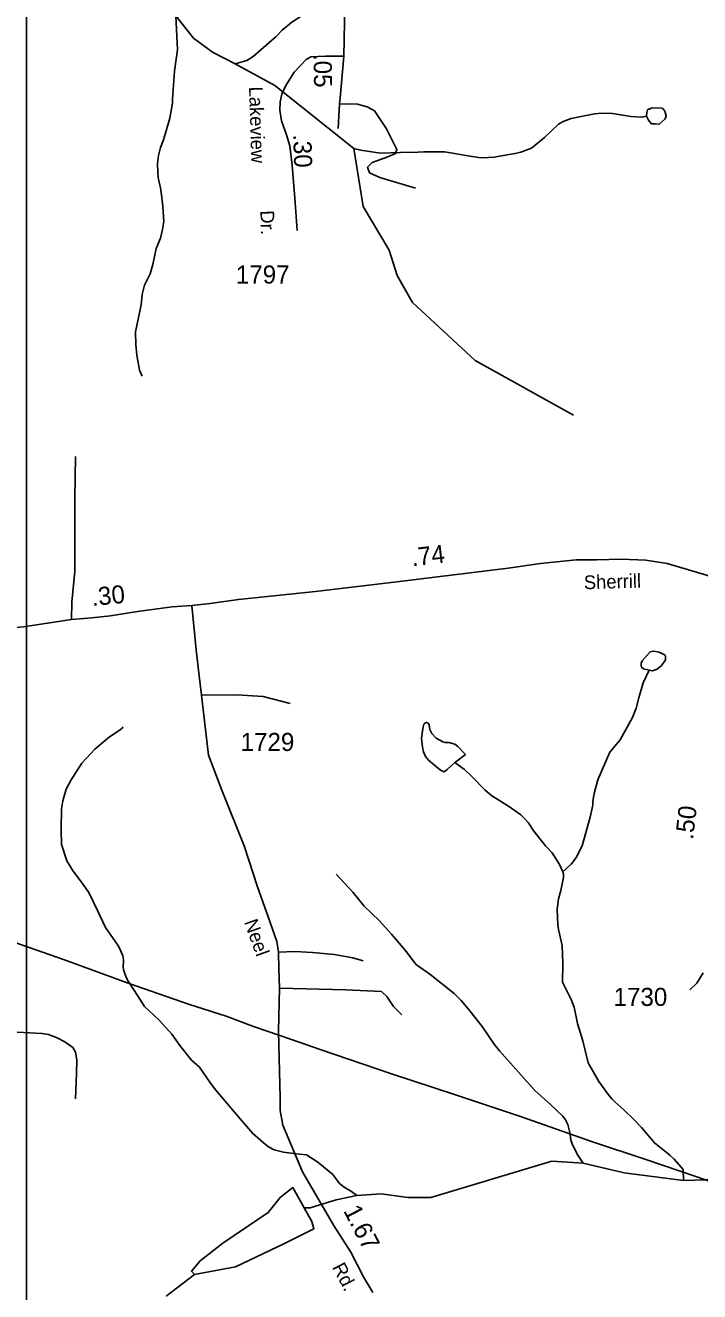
# Model space of a CAD drawing. Extents: x 1473865 to 1648260, y 639067 to 773536.
# Drawn here: x 1530800 to 1535463, y 703860 to 712614 of the extents above; entities that cross this region are included whole.
import ezdxf

# ---------------------------------------------------------------- set-up
doc = ezdxf.new("R2010")
doc.units = 0
for name, color, linetype in [('Exist Hydrographic Creek Single Shore', 7, 'Continuous'), ('Exist Hydrographic Misc Water Feature', 7, 'Continuous'), ('Exist Hydrographic Pond Under 1500 Sq Ft', 7, 'Continuous'), ('Exist Road Non-System Type 51', 7, 'Continuous'), ('Exist Road Secondary Mileage Hundredths English Label', 7, 'Continuous'), ('Exist Road Secondary Type 51 Attributed', 7, 'Continuous'), ('Exist Road Secondary Type 51 Label', 7, 'Continuous'), ('Exist Road Secondary Type 51 Number Label', 7, 'Continuous'), ('Exist Utilities Electrical Transmission Line', 7, 'Continuous'), ('Map Preparation Inset Cut Line', 7, 'Continuous')]:
    doc.layers.add(name, color=color, linetype=linetype)

msp = doc.modelspace()

# ---------------------------------------------------------------- linework, layer by layer
at = {"layer": 'Exist Hydrographic Creek Single Shore'}
for points in [[(1534589.6, 709919.7), (1533911.6, 710297.7), (1533476.6, 710697.1), (1533370.7, 710883.1), (1533315.6, 711058.2), (1533136.6, 711360.5), (1533071.2, 711761.9), (1532524.6, 712196.7), (1532250.4, 712346.9), (1532094.6, 712428.7), (1531963.7, 712525.7), (1531840.7, 712679.1)], [(1537312.6, 702324.8), (1537305.6, 702384), (1537166.6, 702560.8), (1537036.6, 702786.6), (1536651.6, 703227.7), (1536390.6, 703590.8), (1536244.6, 703849.7), (1536031.6, 704103.5), (1535822.6, 704567.3), (1535733.4, 704640.1), (1535350.5, 704627.4), (1534940.5, 704680.2), (1534657.6, 704746.9), (1534441.5, 704762.6), (1533603.6, 704510.3), (1533445.5, 704510.3), (1533260.5, 704535.4), (1533093.2, 704523.7), (1532948.5, 704494.9), (1532769.6, 704438.5), (1532727.5, 704439.4)]]:
    msp.add_lwpolyline(points, dxfattribs=at)
at = {"layer": 'Exist Hydrographic Misc Water Feature'}
for points in [[(1532250.4, 712346.9), (1532330.8, 712371.3), (1532375.3, 712398.4), (1532534.2, 712537.1), (1532575, 712580.2), (1532642, 712634.8), (1532715, 712681.3), (1532757.4, 712702.4), (1532890.5, 712757.8), (1532959, 712782.3), (1533019.2, 712791.1), (1533063.6, 712810.2), (1533133.3, 712900.7), (1533171.1, 712995.9), (1533200.8, 713075.3), (1533237, 713114.4)], [(1531840.7, 712679.1), (1531852.2, 712444.7), (1531841.4, 712363.2), (1531830.5, 712296.2), (1531817.5, 712103.8), (1531817, 712075.9), (1531798.9, 711972.3), (1531790.3, 711940.5), (1531756, 711821.2), (1531735, 711769.7), (1531721.6, 711714.3), (1531712.8, 711658.2), (1531715.6, 711596.1), (1531719, 711562.1), (1531722.5, 711538), (1531733.5, 711489.8), (1531740.6, 711441.7), (1531751.1, 711361.5), (1531757, 711257.4), (1531748, 711201.7), (1531734.8, 711142), (1531705.4, 711070.6), (1531692.3, 711014.9), (1531681.2, 710959.1), (1531662, 710895.6), (1531624.4, 710816.4), (1531607.2, 710752.7), (1531600.1, 710680.9), (1531562.1, 710493.8), (1531564.5, 710405.8), (1531567.5, 710357.7), (1531571, 710333.7), (1531589, 710229.4), (1531608.2, 710189)], [(1533071.2, 711761.9), (1533119, 711749.6), (1533254.2, 711729.2), (1533394.7, 711734), (1533514.8, 711737.5), (1533554.8, 711738.7), (1533594.9, 711739.9), (1533698.8, 711739.8), (1533889.4, 711706.5), (1533950.1, 711698.7), (1534002.1, 711699.6), (1534042.2, 711702.8), (1534066.3, 711706.4), (1534146.6, 711720.7), (1534186.8, 711727.9), (1534227, 711737.1), (1534299.4, 711763.6), (1534389.3, 711838.8), (1534486.8, 711929.7), (1534519.2, 711949), (1534575.5, 711969.9), (1534712.1, 711997.1), (1534736.2, 712000.6), (1534784.3, 712005.6), (1534860.3, 712004.1), (1534987.9, 711983.8), (1535063.8, 711977.9), (1535096.2, 711984.8)], [(1535097.3, 712010.9), (1535096.2, 711984.8), (1535108.7, 711957.9), (1535128.8, 711933), (1535157.9, 711933.7), (1535183.4, 711930.1), (1535224.5, 711968.3), (1535230.9, 711988.2), (1535221.5, 712020.4), (1535207.9, 712038.7), (1535199.9, 712040.8), (1535131.9, 712042.2), (1535115.7, 712034.5), (1535107.7, 712034.7), (1535101.7, 712028.8), (1535097.3, 712010.9)], [(1535113.5, 708154.8), (1535073.7, 708165.5), (1535061.8, 708175.8), (1535058, 708185.8), (1535058.4, 708203.8), (1535064.7, 708219.7), (1535120, 708282.6), (1535144.1, 708288), (1535183.9, 708281.2), (1535223.5, 708258.5), (1535227.4, 708250.4), (1535226.9, 708228.4), (1535218.6, 708212.6), (1535200.1, 708188.9), (1535169.7, 708163.6), (1535137.4, 708152.2), (1535113.5, 708154.8)], [(1534516.7, 706762.8), (1534573.3, 706814.3), (1534587.6, 706832), (1534597.9, 706845.8), (1534608.3, 706861.6), (1534649.8, 706940.7), (1534705.7, 707139.5), (1534723.3, 707223.1), (1534723.7, 707247.1), (1534728.3, 707279), (1534732.8, 707302.9), (1534758.7, 707398.3), (1534842.1, 707588.5), (1534913.6, 707674.4), (1534999.1, 707829.2), (1535024.4, 707892.6), (1535041.7, 707964.3), (1535071.8, 708067.6), (1535113.5, 708154.8)], [(1533093.2, 704523.7), (1533055, 704552.2), (1533003.5, 704581.3), (1532972, 704607.9), (1532925.2, 704668.8), (1532822.9, 704754.8), (1532743.8, 704804.4), (1532695.8, 704809.4), (1532671.9, 704811.9), (1532584.1, 704823.6), (1532520.4, 704841), (1532480.8, 704861.7), (1532461.1, 704876.1), (1532372.9, 704951.9), (1532284.5, 705053.6), (1532116.4, 705253), (1532081.3, 705301.7), (1532003.4, 705411.2), (1531948.3, 705460.3), (1531868.3, 705561.8), (1531811.8, 705639), (1531725.6, 705736.7), (1531623.5, 705830.7), (1531553.6, 705940), (1531506.9, 706013), (1531491.6, 706045.3), (1531480.3, 706077.5), (1531476.7, 706099.6), (1531477.7, 706153.5), (1531474.2, 706181.5), (1531453.2, 706230), (1531439.7, 706254.2), (1531354, 706375.9), (1531300.3, 706489), (1531238.7, 706618.1), (1531182.2, 706699.2), (1531129.5, 706766.3), (1531086.9, 706837.1), (1531049.1, 706949.8), (1531047.1, 707053.8), (1531049.9, 707197.7), (1531059, 707253.5), (1531082.6, 707333), (1531116.8, 707397.9), (1531190.3, 707513.6), (1531280, 707608.9), (1531381.7, 707694.7), (1531454.7, 707743.2), (1531470.9, 707756.9), (1531475.1, 707764.8)], [(1533770.3, 707517.3), (1533776.9, 707522.2), (1533842.7, 707574), (1533790.9, 707627.8), (1533769.3, 707644.3), (1533727.5, 707655.1), (1533703.5, 707655.6), (1533687.6, 707659.9), (1533640, 707686.9), (1533610.7, 707717.5), (1533597.1, 707745.7), (1533591.8, 707777.8), (1533582.1, 707792), (1533574.1, 707794.2), (1533562.1, 707790.4), (1533555.9, 707782.5), (1533549.3, 707750.7), (1533540, 707686.9), (1533546.8, 707622.8), (1533554.2, 707590.7), (1533567.5, 707558.4), (1533587.1, 707534), (1533669.7, 707464.4), (1533695.6, 707453.8), (1533717.8, 707469.4), (1533770.3, 707517.3)], [(1534516.7, 706762.8), (1534493.2, 706812), (1534442.8, 706893), (1534397.8, 706941.8), (1534315.6, 707043.5), (1534276.8, 707102.2), (1534253.3, 707128.7), (1534225.8, 707155.2), (1534141, 707216.9), (1534026.3, 707287.2), (1533980.8, 707326.1), (1533887.5, 707421.6), (1533835.8, 707469), (1533770.3, 707517.3)], [(1534657.6, 704746.9), (1534620.2, 704804.3), (1534581.6, 704879), (1534570.4, 704919.3), (1534567, 704951.3), (1534552.3, 705015.6), (1534534.9, 705047.9), (1534517.4, 705072.3), (1534431, 705154), (1534322.8, 705250.1), (1534078.1, 705525), (1534042.9, 705569.7), (1533959.4, 705693.3), (1533873.4, 705801), (1533814.8, 705872.2), (1533765.7, 705921.1), (1533596.3, 706054.5), (1533505.5, 706118.3), (1533487.8, 706136.7), (1533435.3, 706207.7), (1533359, 706299.2), (1533331.6, 706331.8), (1533247.4, 706425.4), (1533143.3, 706523.5), (1533065.1, 706621.1), (1532949.6, 706745.3)], [(1535350.5, 704627.4), (1535348.4, 704703.6), (1535287.8, 704774.8), (1535256.3, 704803.4), (1535149.9, 704887.5), (1535060, 704993.3), (1535009, 705046.3), (1534938.4, 705117.7), (1534875.4, 705170.9), (1534857.7, 705189.3), (1534832.4, 705219.8), (1534766.1, 705313.1), (1534692.6, 705440.5), (1534655.5, 705593.2), (1534617.9, 705713.9), (1534596.1, 705826.3), (1534577, 705874.7), (1534515.5, 705999.9), (1534517.9, 706127.8), (1534512.3, 706251.8), (1534486.6, 706364.3), (1534483.1, 706394.3), (1534476.7, 706504.7), (1534486.7, 706576.2), (1534503.5, 706632.1), (1534521.5, 706723.4), (1534521.9, 706747.4), (1534516.7, 706762.8)], [(1531969.8, 703978.6), (1531773.1, 703828)]]:
    msp.add_lwpolyline(points, dxfattribs=at)
at = {"layer": 'Exist Hydrographic Pond Under 1500 Sq Ft'}
msp.add_lwpolyline([(1532727.5, 704439.4), (1532781.9, 704343.5), (1532795.9, 704295), (1532738.8, 704267.2), (1532588.3, 704189.1), (1532252.6, 704030.2), (1531969.8, 703978.6), (1531948.6, 704001.5), (1532009, 704073.6), (1532166.2, 704195.7), (1532479.6, 704406.2), (1532561.8, 704510.8), (1532649.6, 704579.1), (1532727.5, 704439.4)], dxfattribs=at)
at = {"layer": 'Exist Road Non-System Type 51'}
for points in [[(1532973.5, 712071.3), (1532962.8, 711901.2)], [(1532976.4, 712112.6), (1532973.5, 712071.3)], [(1532973.5, 712071.3), (1533096.1, 712069.1), (1533162.8, 712049.7), (1533214.4, 712021.8), (1533298.2, 711896.9), (1533369.2, 711754.9), (1533358.5, 711726.9), (1533306.8, 711705.4), (1533199.3, 711664.5), (1533167.1, 711632.2), (1533180, 711593.4), (1533250.9, 711561.1), (1533498.2, 711488)], [(1531119, 708505.7), (1531121.7, 708626.7), (1531141, 708841.2), (1531141, 709341.8), (1531146.5, 709633.4)], [(1532018.5, 707982.1), (1532262.5, 707984.5), (1532445.5, 707974.8), (1532631, 707925.9)], [(1533137.1, 706147.3), (1533065.4, 706166.4), (1532936.5, 706190.9), (1532784.7, 706205.2), (1532664.5, 706210.2), (1532549.8, 706206.4)], [(1535487.4, 706062.6), (1535443.1, 705991.7), (1535394.4, 705946.5)], [(1532557.1, 705958.6), (1533016, 705946.4), (1533262.4, 705934.2), (1533299.1, 705900), (1533345.4, 705831.6), (1533404, 705773)], [(1530360.9, 705649.1), (1530745.5, 705652.4), (1530915.2, 705643.4), (1530960.5, 705636.7), (1531020.6, 705615), (1531072.5, 705586.8), (1531128.8, 705547.8), (1531146.1, 705515.3), (1531157, 705461.2), (1531152.6, 705368), (1531146.1, 705192.5)]]:
    msp.add_lwpolyline(points, dxfattribs=at)
at = {"layer": 'Exist Road Secondary Type 51 Attributed'}
for points in [[(1533044.4, 714294.5), (1533029.3, 713564.5), (1533020.3, 713242), (1533006.3, 712637.2), (1533002.3, 712397.9)], [(1533002.5, 712399.4), (1532875.1, 712399.9), (1532773, 712394.9), (1532743, 712377.8), (1532659.3, 712288.7), (1532601.3, 712197.6), (1532573.2, 712137.5), (1532562.2, 712084.4), (1532560.2, 712027.4), (1532570.7, 711953.3), (1532605.8, 711856.1), (1532627.8, 711780), (1532644.8, 711646.8), (1532666.3, 711388.5), (1532679.4, 711196.2)], [(1533002.3, 712397.9), (1532976.4, 712112.6)], [(1531952.3, 708603.5), (1532078.5, 708617.6), (1532274.9, 708644.6), (1532805.9, 708700.5), (1533368.9, 708765.8), (1534138.6, 708862.1), (1534361.2, 708892.8), (1534609.4, 708919), (1534749.5, 708918.8), (1534921.7, 708924.1), (1535091.6, 708915.5), (1535239.2, 708893.3), (1535510.1, 708813), (1535721.6, 708730.3), (1535781, 708703.6)], [(1530550.5, 708434), (1530786.1, 708456.1), (1531119, 708505.7), (1531259.1, 708516.7), (1531388.3, 708530.4), (1531576.5, 708560.7), (1531814.8, 708593.5), (1531952.3, 708603.5)], [(1531952.3, 708603.5), (1531981.9, 708297.4), (1532001.2, 708117.1), (1532018.5, 707982.1), (1532067.3, 707569.3), (1532158.8, 707327.3), (1532313.2, 706940.9), (1532404.8, 706657), (1532479.5, 706451.6), (1532539.1, 706280.7), (1532549.8, 706206.4), (1532552.3, 706090.5), (1532557.1, 705958.6), (1532549.8, 705660.7), (1532562.2, 705196.1), (1532562.1, 705112.6), (1532581.6, 705011.6), (1532717, 704688.9), (1532935.1, 704313.1), (1533049.7, 704133.2), (1533140, 703957.3), (1533203.4, 703854.8)]]:
    msp.add_lwpolyline(points, dxfattribs=at)
at = {"layer": 'Exist Utilities Electrical Transmission Line'}
msp.add_lwpolyline([(1538029.3, 703759.2), (1537494.4, 703944.5), (1537058.8, 704096.1), (1536631.1, 704239.6), (1536215.6, 704390.9), (1535843.6, 704513.3), (1535443.9, 704654.4), (1535091.7, 704772.4), (1534721.8, 704894.9), (1534224.7, 705069.6), (1533775.1, 705221.4), (1533331.4, 705365.2), (1532838.2, 705533.9), (1532641.3, 705603.3), (1532378.7, 705691.8), (1532187.9, 705763.3), (1531929.2, 705847.8), (1531511.8, 705993.1), (1531064.4, 706154.8), (1530640.8, 706304.2)], dxfattribs=at)
at = {"layer": 'Map Preparation Inset Cut Line'}
msp.add_lwpolyline([(1530807.2, 678673.7), (1530807.2, 722115.9), (1605695.7, 722115.9), (1605695.7, 695030), (1593323.3, 695030), (1593323.3, 678673.7), (1530807.2, 678673.7)], dxfattribs=at)

# ---------------------------------------------------------------- texts
at = {"layer": 'Exist Road Secondary Mileage Hundredths English Label'}
for s, rotation, p in [('.05', 271.02577, (1532792.8, 712414.7)), ('.30', 271.74582, (1532652.2, 711859.8)), ('.74', 6.61313, (1533475.6, 708873.7)), ('.30', 5.54774, (1531262.5, 708599.1)), ('.50', 83.26785, (1535416.9, 706980.8)), ('1.67', 297.47532, (1532996.4, 704419.7))]:
    msp.add_text(s, height=125, rotation=rotation, dxfattribs=at).set_placement(p)
at = {"layer": 'Exist Road Secondary Type 51 Label'}
for s, rotation, p in [('Lakeview', 271.74582, (1532346.6, 712189)), ('Dr.', 271.75319, (1532425, 711333.3)), ('Sherrill', 1.7712, (1534663.5, 708714.8)), ('Neel', 289.69169, (1532311.5, 706415.2)), ('Rd.', 297.48436, (1532919.5, 704029.1))]:
    msp.add_text(s, height=95, rotation=rotation, dxfattribs=at).set_placement(p)
at = {"layer": 'Exist Road Secondary Type 51 Number Label'}
for s, p in [('1797', (1532255.4, 710828.5)), ('1729', (1532288.3, 707597.3)), ('1730', (1534867.3, 705834.8))]:
    msp.add_text(s, height=125, dxfattribs=at).set_placement(p)

doc.saveas('drawing.dxf')
